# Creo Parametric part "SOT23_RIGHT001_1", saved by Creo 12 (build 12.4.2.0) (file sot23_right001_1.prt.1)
Units: Custom; MM, KILOGRAM, SECS

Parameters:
  PTC_WM_ITERATION = "0"
  PTC_WM_VERSION = "-.0"
  PTC_WM_LIFECYCLE_STATE = "In Work"
  PTC_WM_LIFECYCLE = "MO_CADDocument"
  PTC_WM_CREATED_BY = "Maximilian Roepper (Z0017RMS: MO)"
  PTC_WM_CREATED_ON = "18-Sep-26 11:36:42 AM"
  PTC_WM_MODIFIED_BY = "Maximilian Roepper (Z0017RMS: MO)"
  PTC_WM_MODIFIED_ON = "18-Sep-26 11:36:46 AM"
  PDMLINKNUMBER = "PDM000071454989"
  PTC_WM_NAME = "sot23_right001_1.prt"
  PTC_WM_NUMBER = "PDM000071454989"

Other parameters: WEIGHT, WEIGHT_FACTOR, WEIGHT_ADD, _MASS_TEMP, _DIFF_TEMP, MC_ERRORS, SUPPLIER

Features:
  1. coordinate system
  2. datum plane "PRT_YZ"
  3. datum plane "PRT_XY"
  4. datum plane "PRT_XZ"
  5. coordinate system
  6. datum axis
  7. datum axis
  8. datum axis
  9. coordinate system
  10. imported feature

Other named items: PRT, SIEMENS_MO, DRW_VIEW_ORG, PRT_X, PRT_Y, PRT_Z, CS0, ROUGH_GROB

Layers: 00_STD_CSYS-KSYS, 01_STD_PLANES-EBENEN, 02_STD_AXES-ACHSEN, 03_STD_CSYS-KSYS, 24_IMPORT_FEAT-IMPORT_KE

Surfaces: 8 plane, 2 cylinder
